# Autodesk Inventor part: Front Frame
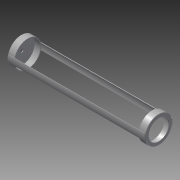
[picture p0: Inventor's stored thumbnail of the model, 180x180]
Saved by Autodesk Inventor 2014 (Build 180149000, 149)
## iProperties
Created: 2009-03
Part Number: Front Frame
Document SubType Name: Modeling
Designer: tangg
Density: 7.86 g/cm^3
Material: Steel, Mild
Mass: 173.384 g
Surface Area: 347.527 cm^2
Volume: 22.059 cm^3
Appearance: Steel
Author: tangg
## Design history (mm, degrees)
sketch "Sketch1"
  geometry: L1 (-14.427, -29.5)-(-1, -29.5); L2 (0, -28.5)-(0, 0); L3 (0, 0)-(-1.5, 0); L4 (-14.427, -28)-(-14.427, -29.5); L5 (-14.427, -28)-(-1.5, -28); L6 (-1.5, -28)-(-1.5, 0); L7 (-1.5, 0)-(-17.075, 0); L8 (-150, -53.823)-(-150, 38.657); L9 (-285.573, -29.5)-(-299, -29.5); L10 (-300, -28.5)-(-300, 0); L11 (-300, 0)-(-298.5, 0); L12 (-285.573, -28)-(-285.573, -29.5); L13 (-285.573, -28)-(-298.5, -28); L14 (-298.5, -28)-(-298.5, 0); L15 (-298.5, 0)-(-282.925, 0); A1 r 1 centre (-1, -28.5) between (-1, -29.5) and (0, -28.5); A2 r 1 centre (-299, -28.5) between (-300, -28.5) and (-299, -29.5); 2 further points
  constraints: 30 end point, 7 symmetric about line, 4 point on circle, 4 point on line, 4 tangent, 3 parallel, 3 perpendicular, 2 centre point, 2 horizontal
  dimensions: "d1" = 1.5 distance between parallel lines of L2 L6; "d2" = 1.5 distance between parallel lines of L1 L5; "d3" = 150 distance from line of L8 L2.end; "d13" = 28 distance from line of L5 L3.end; "d14" = 1 radius of A1; "d15" = 1 radius of A2
revolve "Revolution1" sketch "Sketch1" stored, may be unused: angle "d0" = 90 deg
sketch "Sketch2"
  geometry: C1 r 3.525 at (0, 0); C2 r 29.5 at (0, 0) reference; C3 r 29.5 at (0, 0) reference
  constraints: 1 centre point
  dimensions: "d4" = 7.05 diameter of C1
extrude "Extrusion1" cut sketch "Sketch2" distance "d5" = 10; taper "d6" = 0 deg
sketch "Sketch3"
  geometry: C1 r 29.5 at (0, 0) reference; C2 r 22.086 at (0, 0); 1 further point
  constraints: 1 centre point
extrude "Extrusion2" cut sketch "Sketch3" distance "d8" = 10; taper "d9" = 0 deg
workplane "Work Plane1"
sketch "Sketch4"
  geometry: L1 (25.167, -7.002)-(24.114, -7.26); L2 (25.167, 7.002)-(24.114, 7.26); L3 (24.114, -7.26)-(25.167, -7.002); L4 (82.48, 7.002)-(83.533, 7.26); L5 (24.114, 7.26)-(25.167, 7.002); L6 (82.48, -7.002)-(83.533, -7.26); A1 r 30.584 centre (53.823, 0) between (24.114, 7.26) and (24.114, -7.26); A2 r 30.584 centre (53.823, 0) between (83.533, -7.26) and (83.533, 7.26); A3 r 29.5 centre (53.823, 0) between (82.48, 7.002) and (82.48, -7.002) reference; 2 further points
  constraints: 12 end point, 8 point on circle, 2 centre point, 2 coincident, 2 collinear, 3 other
extrude "Extrusion3" join sketch "Sketch4" stored distance "d11" = 298; taper "d12" = 0 deg
body "Solid1"
node "Projected Loop1"
other parameters: "d10" = 0
